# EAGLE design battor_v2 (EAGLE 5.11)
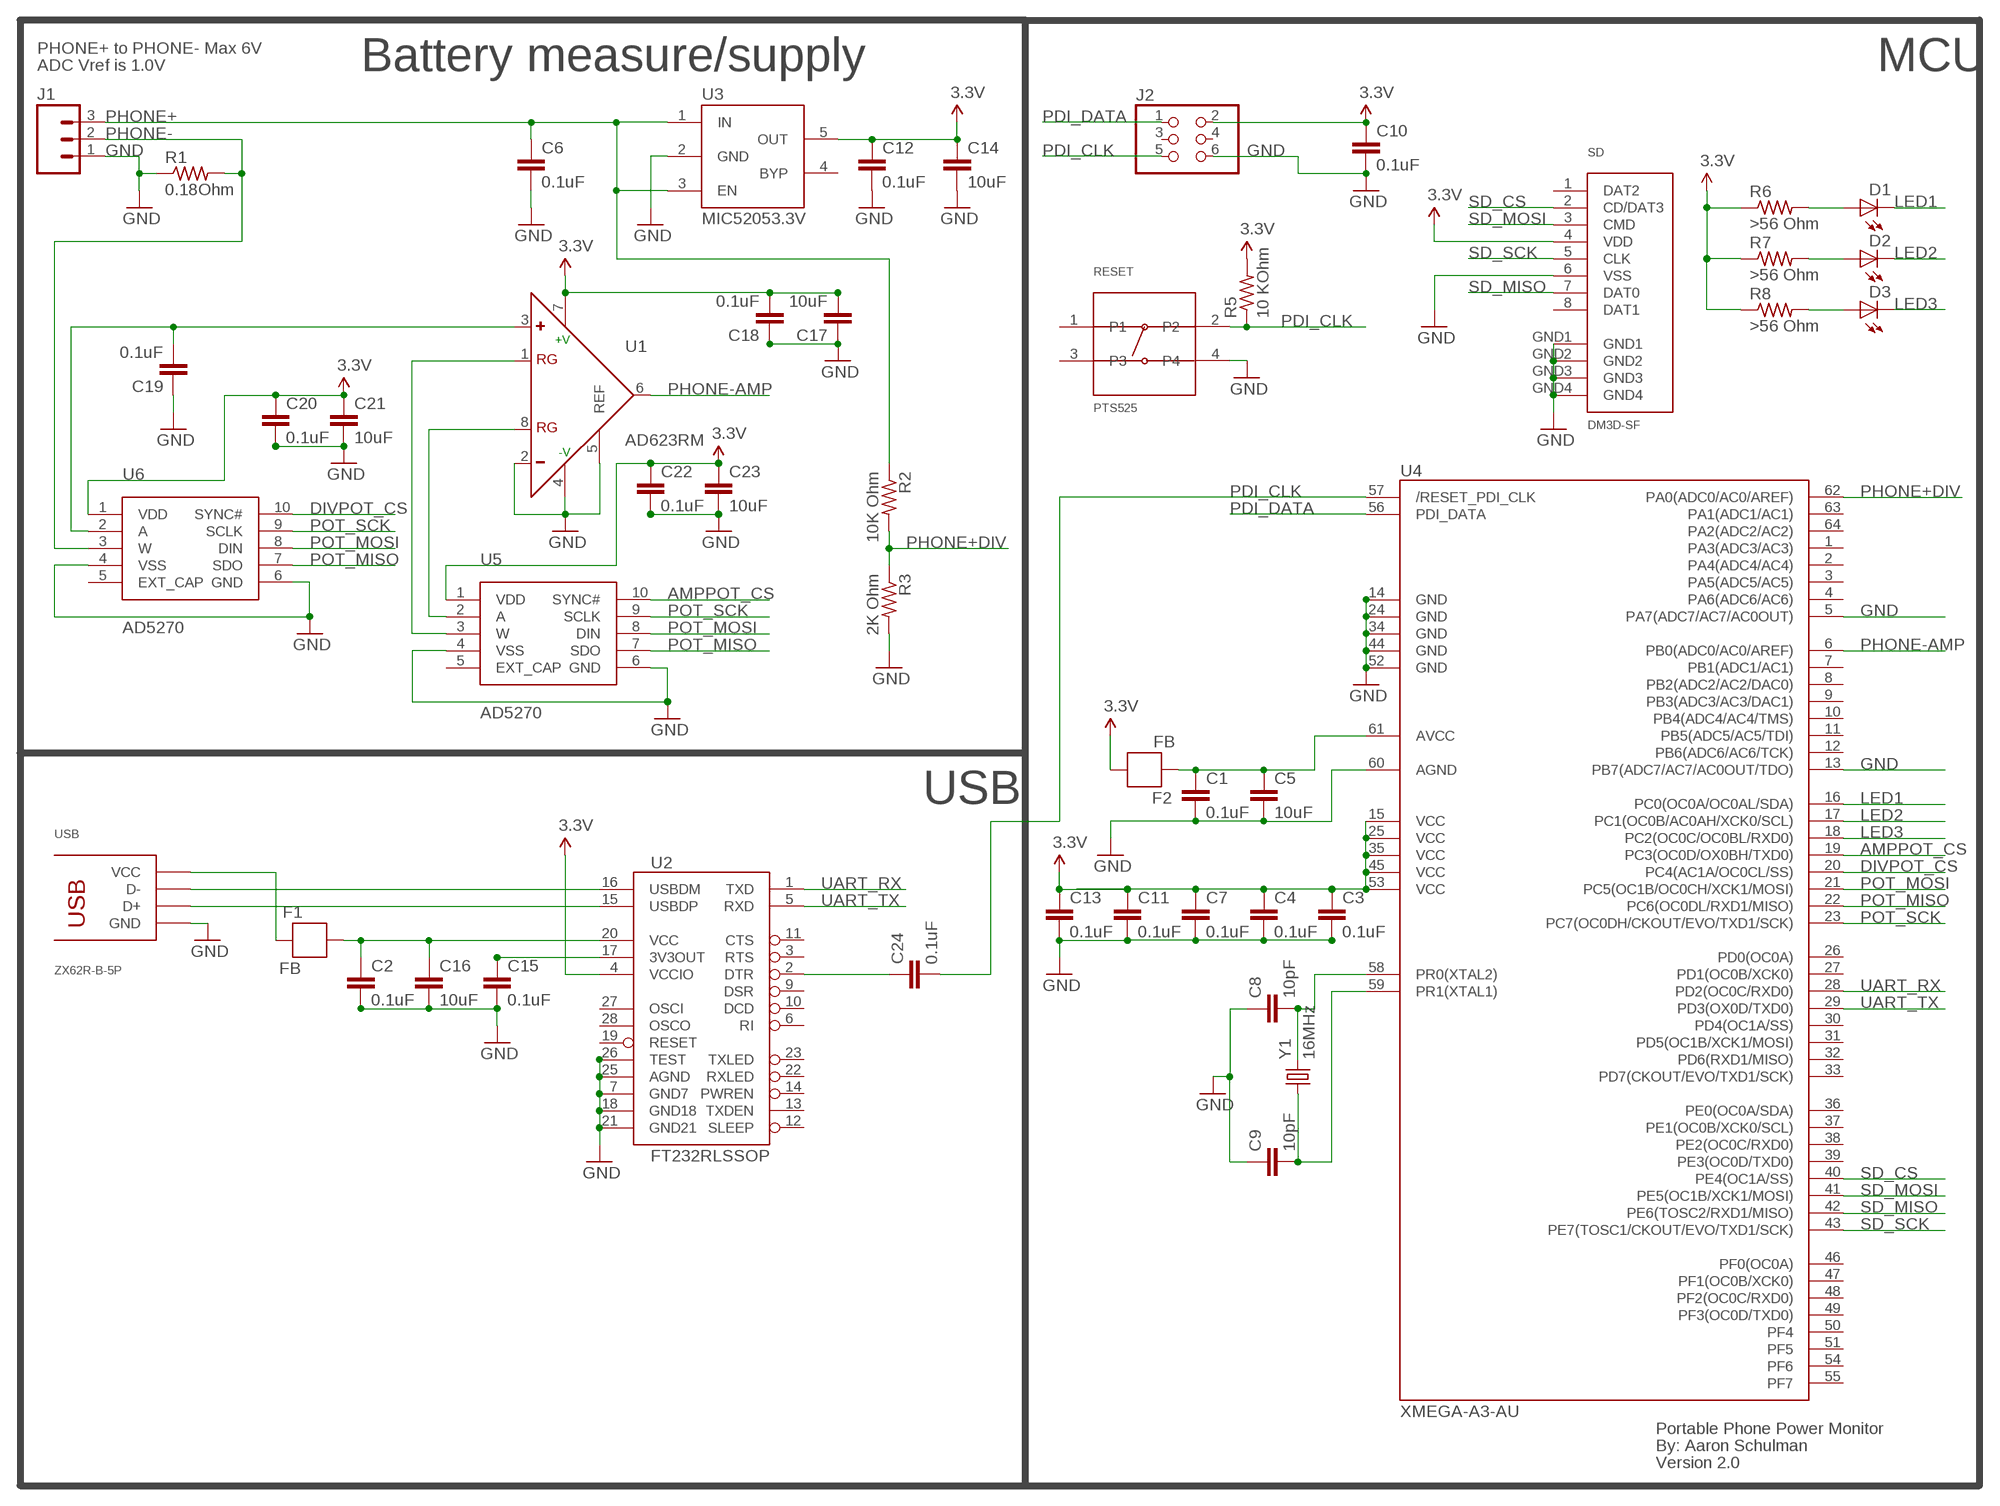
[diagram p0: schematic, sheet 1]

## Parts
C1  0.1uF  CAP0603-CAP  [0603-CAP]
C2  0.1uF  CAP0603-CAP  [0603-CAP]
C3  0.1uF  CAP0603-CAP  [0603-CAP]
C4  0.1uF  CAP0603-CAP  [0603-CAP]
C5  10uF  CAP0603-CAP  [0603-CAP]
C6  0.1uF  CAP0603-CAP  [0603-CAP]
C7  0.1uF  CAP0603-CAP  [0603-CAP]
C8  10pF  CAP0603-CAP  [0603-CAP]
C9  10pF  CAP0603-CAP  [0603-CAP]
C10  0.1uF  CAP0603-CAP  [0603-CAP]
C11  0.1uF  CAP0603-CAP  [0603-CAP]
C12  0.1uF  CAP0603-CAP  [0603-CAP]
C13  0.1uF  CAP0603-CAP  [0603-CAP]
C14  10uF  CAP0603-CAP  [0603-CAP]
C15  0.1uF  CAP0603-CAP  [0603-CAP]
C16  10uF  CAP0603-CAP  [0603-CAP]
C17  10uF  CAP0603-CAP  [0603-CAP]
C18  0.1uF  CAP0603-CAP  [0603-CAP]
C19  0.1uF  CAP0603-CAP  [0603-CAP]
C20  0.1uF  CAP0603-CAP  [0603-CAP]
C21  10uF  CAP0603-CAP  [0603-CAP]
C22  0.1uF  CAP0603-CAP  [0603-CAP]
C23  10uF  CAP0603-CAP  [0603-CAP]
C24  0.1uF  CAP0603-CAP  [0603-CAP]
D1  LED0603  [LED-0603]
D2  LED0603  [LED-0603]
D3  LED0603  [LED-0603]
F1  FB  [0603]
F2  FB  [0603]
J1  M03PTH  [1X03]
J2  PINHD-2X3  [2X03]
R1  0.18Ohm  R-US_R2512  [R2512]
R2  10K Ohm  R-US_R0603  [R0603]
R3  2K Ohm  R-US_R0603  [R0603]
R5  10 KOhm  R-US_R0603  [R0603]
R6  >56 Ohm  R-US_R0603  [R0603]
R7  >56 Ohm  R-US_R0603  [R0603]
R8  >56 Ohm  R-US_R0603  [R0603]
RESET  PTS525  [PT525]
SD  DM3D-SF  [DM3D-SF]
U1  AD623RM  [MSOP08]
U2  FT232RLSSOP  [SSOP28DB]
U3  MIC52053.3V  [SOT23-5]
U4  XMEGA-A3-AU  [TQFP64_14X14MM]
U5  AD5270  [MSOP10]
U6  AD5270  [MSOP10]
USB  ZX62R-B-5P  [ZX62R-B-5P]
Y1  16MHz  CRYSTAL5X3  [CRYSTAL-SMD-5X3]

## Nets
3.3V: C3.1 C4.1 C7.1 C10.1 C11.1 C12.1 C13.1 C14.1 C17.2 C18.2 C20.1 C21.1 C22.1 C23.1 F2.1 J2.2 R5.2 R6.1 R7.1 R8.1 SD.4(VDD) U1.7(+V) U2.4(VCCIO) U3.5(OUT) U4.15(VCC1) U4.25(VCC2) U4.35(VCC3) U4.45(VCC4) U4.53(VCC5) U5.1(VDD) U6.1(VDD)
AMPPOT_CS: U4.19(PC3(OC0D/OX0BH/TXD0)) U5.10(SYNC#)
DIVPOT_CS: U4.20(PC4(AC1A/OC0CL/SS)) U6.10(SYNC#)
GND: C1.2 C2.2 C3.2 C4.2 C5.2 C6.2 C7.2 C8.1 C9.1 C10.2 C11.2 C12.2 C13.2 C14.2 C15.2 C16.2 C17.1 C18.1 C19.1 C20.2 C21.2 C22.2 C23.2 J1.1 J2.6 R1.1 R3.2 RESET.4 SD.6(VSS) SD.GND1 SD.GND2 SD.GND3 SD.GND4 U1.2(-) U1.4(-V) U1.5(REF) U2.7(GND7) U2.18(GND18) U2.21(GND21) U2.25(AGND) U2.26(TEST) U3.2(GND) U4.5(PA7(ADC7/AC7/AC0OUT)) U4.13(PB7(ADC7/AC7/AC0OUT/TDO)) U4.14(GND1) U4.24(GND2) U4.34(GND3) U4.44(GND4) U4.52(GND5) U4.60(AGND) U5.4(VSS) U5.6(GND) U6.4(VSS) U6.6(GND) USB.P$5(GND)
LED1: D1.C U4.16(PC0(OC0A/OC0AL/SDA))
LED2: D2.C U4.17(PC1(OC0B/AC0AH/XCK0/SCL))
LED3: D3.C U4.18(PC2(OC0C/OC0BL/RXD0))
N$1: C8.2 U4.58(PR0(XTAL2)) Y1.3
N$2: C1.1 C5.1 F2.2 U4.61(AVCC)
N$3: C24.1 U2.2(DTR)
N$5: C19.2 U1.3(+) U6.2(A)
N$6: D1.A R6.2
N$7: U2.16(USBDM) USB.P$2(D-)
N$9: C9.2 U4.59(PR1(XTAL1)) Y1.1
N$11: U2.15(USBDP) USB.P$3(D+)
N$12: F1.2 USB.P$1(VCC)
N$13: C15.1 U2.17(3V3OUT)
N$14: C2.1 C16.1 F1.1 U2.20(VCC)
N$17: D3.A R8.2
N$18: D2.A R7.2
N$21: U1.8(RG) U5.2(A)
N$24: U1.1(RG) U5.3(W)
PDI_CLK: C24.2 J2.5 R5.1 RESET.2 U4.57(/RESET_PDI_CLK)
PDI_DATA: J2.1 U4.56(PDI_DATA)
PHONE+: C6.1 J1.3 R2.1 U3.1(IN) U3.3(EN)
PHONE+DIV: R2.2 R3.1 U4.62(PA0(ADC0/AC0/AREF))
PHONE-: J1.2 R1.2 U6.3(W)
PHONE-AMP: U1.6(OUT) U4.6(PB0(ADC0/AC0/AREF))
POT_MISO: U4.22(PC6(OC0DL/RXD1/MISO)) U5.7(SDO) U6.7(SDO)
POT_MOSI: U4.21(PC5(OC1B/OC0CH/XCK1/MOSI)) U5.8(DIN) U6.8(DIN)
POT_SCK: U4.23(PC7(OC0DH/CKOUT/EVO/TXD1/SCK)) U5.9(SCLK) U6.9(SCLK)
SD_CS: SD.2(CD/DAT3) U4.40(PE4(OC1A/SS))
SD_MISO: SD.7(DAT0) U4.42(PE6(TOSC2/RXD1/MISO))
SD_MOSI: SD.3(CMD) U4.41(PE5(OC1B/XCK1/MOSI))
SD_SCK: SD.5(CLK) U4.43(PE7(TOSC1/CKOUT/EVO/TXD1/SCK))
UART_RX: U2.1(TXD) U4.28(PD2(OC0C/RXD0))
UART_TX: U2.5(RXD) U4.29(PD3(OX0D/TXD0))
Unconnected: J2.3 J2.4 RESET.1 RESET.3 SD.1(DAT2) SD.8(DAT1) U2.3(RTS) U2.6(RI) U2.9(DSR) U2.10(DCD) U2.11(CTS) U2.12(SLEEP) U2.13(TXDEN) U2.14(PWREN) U2.19(RESET) U2.22(RXLED) U2.23(TXLED) U2.27(OSCI) U2.28(OSCO) U3.4(BYP) U4.1(PA3(ADC3/AC3)) U4.2(PA4(ADC4/AC4)) U4.3(PA5(ADC5/AC5)) U4.4(PA6(ADC6/AC6)) U4.7(PB1(ADC1/AC1)) U4.8(PB2(ADC2/AC2/DAC0)) U4.9(PB3(ADC3/AC3/DAC1)) U4.10(PB4(ADC4/AC4/TMS)) U4.11(PB5(ADC5/AC5/TDI)) U4.12(PB6(ADC6/AC6/TCK)) U4.26(PD0(OC0A)) U4.27(PD1(OC0B/XCK0)) U4.30(PD4(OC1A/SS)) U4.31(PD5(OC1B/XCK1/MOSI)) U4.32(PD6(RXD1/MISO)) U4.33(PD7(CKOUT/EVO/TXD1/SCK)) U4.36(PE0(OC0A/SDA)) U4.37(PE1(OC0B/XCK0/SCL)) U4.38(PE2(OC0C/RXD0)) U4.39(PE3(OC0D/TXD0)) U4.46(PF0(OC0A)) U4.47(PF1(OC0B/XCK0)) U4.48(PF2(OC0C/RXD0)) U4.49(PF3(OC0D/TXD0)) U4.50(PF4) U4.51(PF5) U4.54(PF6) U4.55(PF7) U4.63(PA1(ADC1/AC1)) U4.64(PA2(ADC2/AC2)) U5.5(EXT_CAP) U6.5(EXT_CAP)

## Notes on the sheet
- PHONE+ to PHONE- Max 6V
- ADC Vref is 1.0V | Battery measure/supply | MCU
- USB
- Portable Phone Power Monitor
- By: Aaron Schulman
- Version 2.0

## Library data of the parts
C1-C24 = SparkFun:CAP: Capacitor
D1-D3 = SparkFun:LED: LEDs
F1 F2 = SparkFun:FB
J1 = SparkFun:M03: Header 3 Standard 3-pin 0.1" header. Use with straight break away headers (SKU : PRT-00116), right angle break away headers (PRT-00553), swiss pins (PRT-00743), machine pins (PRT-00117), and female headers (PRT-00115). Molex polarized connector foot print use with SKU : PRT-08232 with associated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
J2 = SparkFun:PINHD-2X3: PIN HEADER
R1 = resistor:R-US_: RESISTOR, American symbol
R2 R3 R5-R8 = rcl:R-US_: RESISTOR, American symbol
RESET = phone_power_monitor:PTS525
SD = phone_power_monitor:DM3D-SF
U1 = analog-devices:AD623: Single-Supply, Rail-to-Rail, Low Cost Instrumentation Amplifier Source: http://www.analog.com/static/imported-files/data_sheets/AD623.pdf; MPN: AD623ARMZ; OC_FARNELL: 1660961; OC_NEWARK: 19M8824
U2 = SparkFun:FT232RL: USB UART FT232RL 4th Generation USB UART (USB <-> Serial) Controller. Spark Fun Electronics SKU : COM-00650
U3 = phone_power_monitor:MIC5205
U4 = SparkFun:XMEGA-A3: Atmel's 8/16-bit AVR XMEGA A3 Microcontroller - ATxmega256A3, etc.
U5 U6 = battor_v2:AD5270
USB = battor_v2:ZX62R-B-5P
Y1 = SparkFun:CRYSTAL: Crystals

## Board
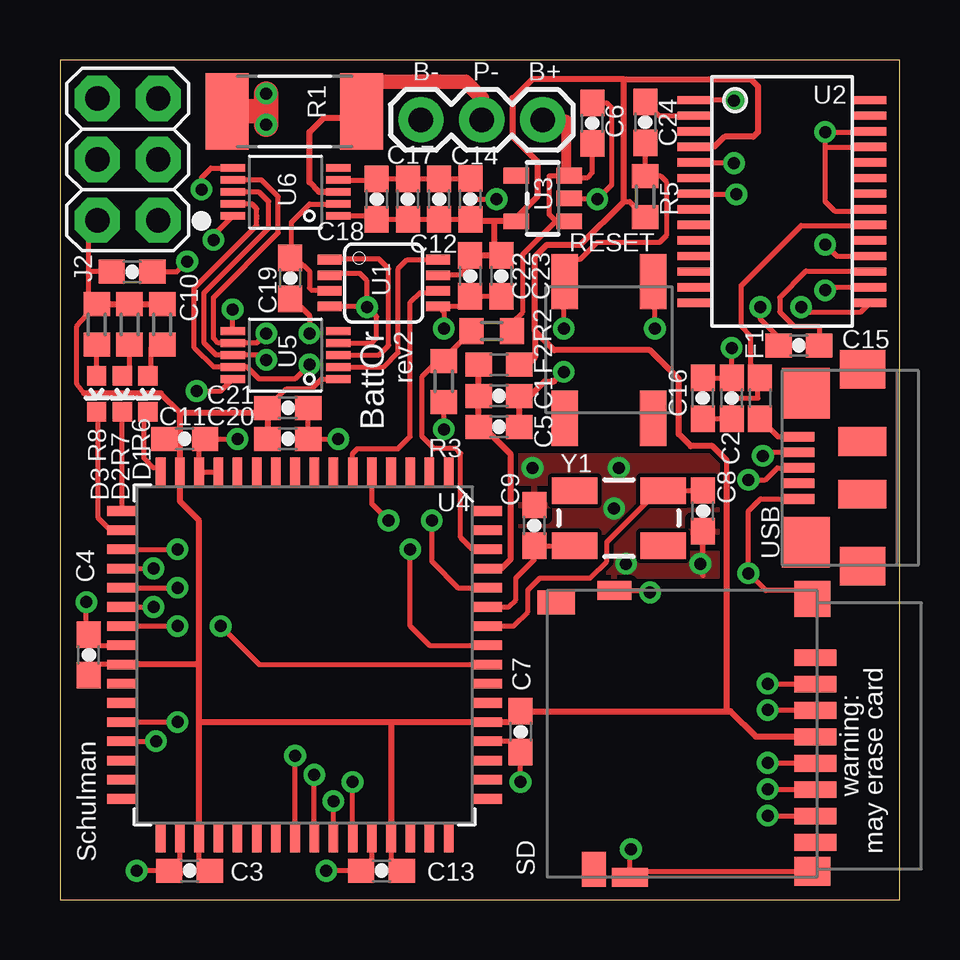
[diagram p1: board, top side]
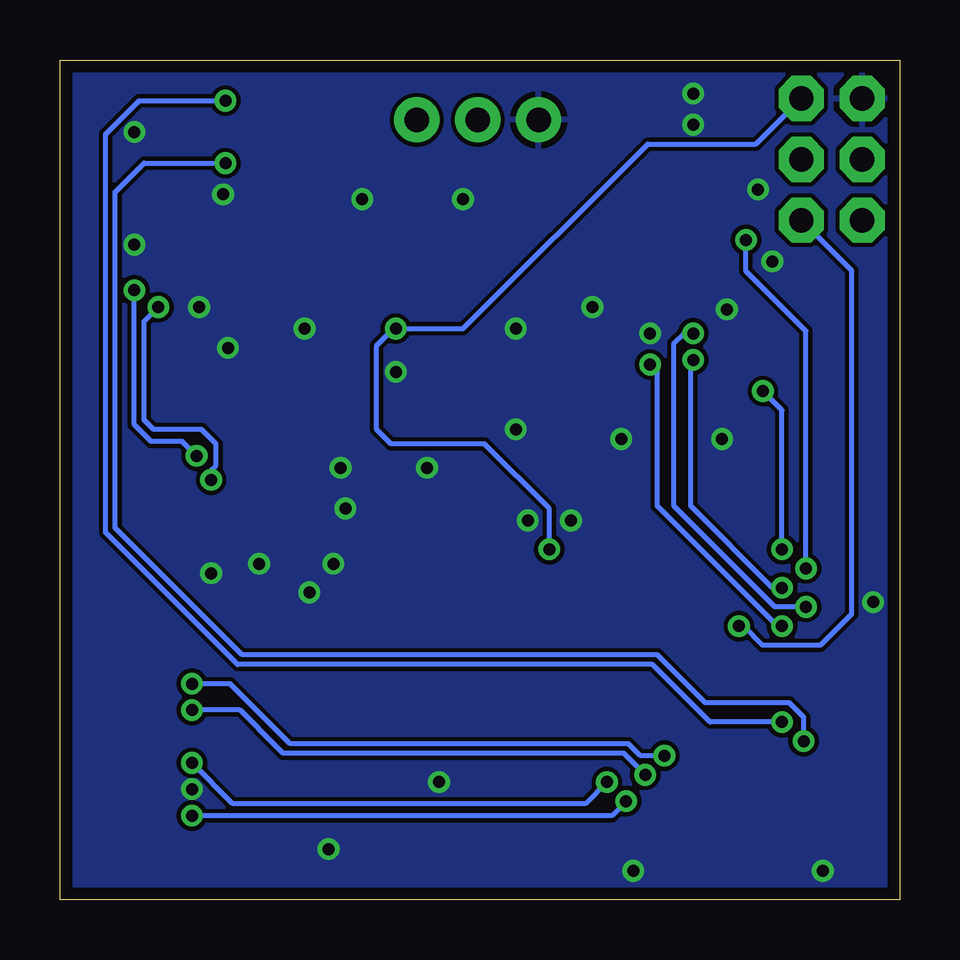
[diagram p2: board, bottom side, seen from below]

Size 35 x 35 mm. Coordinates in mm from the lower left corner, seen from the top.
Outline: 0,0 35,0 35,35 0,35 0,0
Copper layers (1*16): Top 0.0178mm / dielectric 1.4986mm / Bottom 0.0178mm
Design rules "SSC-EAGLE-2Lyr_v1.0.0.3 *": minimum track width 6mil, minimum drill 14mil, track to track 7mil, track to pad 7mil, pad to pad 7mil, via to via 7mil, smd to smd 7mil, copper to edge 20mil, drill to drill 16mil, minimum pad ring 8mil, minimum via ring 8mil, stop-mask expansion 3mil, vias tented up to drill 0mil, thermal gap 10mil

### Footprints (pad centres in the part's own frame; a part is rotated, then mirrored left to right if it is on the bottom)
0603-CAP = smd 1.1 x 1: 1 -0.85,0; 2 0.85,0
LED-0603 = smd 0.8 x 0.8: A 0,-0.75; C 0,0.75
0603 = smd 1.1 x 1: 1 -0.85,0; 2 0.85,0
1X03 = drill 1.016 pad 1.88 round: 1 0,0; 2 2.54,0; 3 5.08,0
2X03 = drill 1.016 pad 1.88 octagon: 1 -2.54,-1.27; 2 -2.54,1.27; 3 0,-1.27; 4 0,1.27; 5 2.54,-1.27; 6 2.54,1.27
R2512 = smd 1.8 x 3.2: 1 -2.8,0; 2 2.8,0
R0603 = smd 1 x 1.1: 1 -0.85,0; 2 0.85,0
PT525 = smd 2.3 x 1.1: 1 -2.85,1.85; 2 2.85,1.85; 3 -2.85,-1.85; 4 2.85,-1.85
DM3D-SF = smd 0.7 x 1.75: 1 7.7,-0.875; 2 6.6,-0.875; 3 5.5,-0.875; 4 4.4,-0.875; 5 3.3,-0.875; 6 2.2,-0.875; 7 1.1,-0.875; 8 0,-0.875 | smd 0.8 x 1.5: GND1 -1.45,6.85 | smd 0.8 x 1.4: GND2 10.5,7.5 | smd 1.5 x 1.5: GND3 10.15,-0.75 | smd 1.2 x 1.5: GND4 -1.2,-0.75 | smd 1 x 1.55: P$4 10,9.925 | smd 1.45 x 1: P$5 -1.125,8.35
MSOP08 = smd 0.4 x 1: 1 -0.976,-2.263; 2 -0.326,-2.263; 3 0.324,-2.263; 4 0.974,-2.263; 5 0.974,2.262; 6 0.324,2.262; 7 -0.326,2.262; 8 -0.976,2.262
SSOP28DB = smd 0.348 x 1.397: 1 -4.225,-3.656; 2 -3.575,-3.656; 3 -2.925,-3.656; 4 -2.275,-3.656; 5 -1.625,-3.656; 6 -0.975,-3.656; 7 -0.325,-3.656; 8 0.325,-3.656; 9 0.975,-3.656; 10 1.625,-3.656; 11 2.275,-3.656; 12 2.925,-3.656; 13 3.575,-3.656; 14 4.225,-3.656; 15 4.225,3.656; 16 3.575,3.656; 17 2.925,3.656; 18 2.275,3.656; 19 1.625,3.656; 20 0.975,3.656; 21 0.325,3.656; 22 -0.325,3.656; 23 -0.975,3.656; 24 -1.625,3.656; 25 -2.275,3.656; 26 -2.925,3.656; 27 -3.575,3.656; 28 -4.225,3.656
SOT23-5 = smd 0.65 x 1.06: 1 0.95,1.1; 2 0,1.1; 3 -0.95,1.1; 4 -0.95,-1.1; 5 0.95,-1.1
TQFP64_14X14MM = smd 0.4 x 1.27: 1 -6,-7.6; 2 -5.2,-7.6; 3 -4.4,-7.6; 4 -3.6,-7.6; 5 -2.8,-7.6; 6 -2,-7.6; 7 -1.2,-7.6; 8 -0.4,-7.6; 9 0.4,-7.6; 10 1.2,-7.6; 11 2,-7.6; 12 2.8,-7.6; 13 3.6,-7.6; 14 4.4,-7.6; 15 5.2,-7.6; 16 6,-7.6; 33 6,7.6; 34 5.2,7.6; 35 4.4,7.6; 36 3.6,7.6; 37 2.8,7.6; 38 2,7.6; 39 1.2,7.6; 40 0.4,7.6; 41 -0.4,7.6; 42 -1.2,7.6; 43 -2,7.6; 44 -2.8,7.6; 45 -3.6,7.6; 46 -4.4,7.6; 47 -5.2,7.6; 48 -6,7.6 | smd 1.27 x 0.4: 17 7.6,-6; 18 7.6,-5.2; 19 7.6,-4.4; 20 7.6,-3.6; 21 7.6,-2.8; 22 7.6,-2; 23 7.6,-1.2; 24 7.6,-0.4; 25 7.6,0.4; 26 7.6,1.2; 27 7.6,2; 28 7.6,2.8; 29 7.6,3.6; 30 7.6,4.4; 31 7.6,5.2; 32 7.6,6; 49 -7.6,6; 50 -7.6,5.2; 51 -7.6,4.4; 52 -7.6,3.6; 53 -7.6,2.8; 54 -7.6,2; 55 -7.6,1.2; 56 -7.6,0.4; 57 -7.6,-0.4; 58 -7.6,-1.2; 59 -7.6,-2; 60 -7.6,-2.8; 61 -7.6,-3.6; 62 -7.6,-4.4; 63 -7.6,-5.2; 64 -7.6,-6
MSOP10 = smd 0.32 x 1.02: 1 -1,-2.2; 2 -0.5,-2.2; 3 0,-2.2; 4 0.5,-2.2; 5 1,-2.2; 6 1,2.2; 7 0.5,2.2; 8 0,2.2; 9 -0.5,2.2; 10 -1,2.2
ZX62R-B-5P = smd 0.4 x 1.35: P$1 1.3,-0.675; P$2 0.65,-0.675; P$3 0,-0.675; P$4 -0.65,-0.675; P$5 -1.3,-0.675 | smd 2.1 x 2: P$6 -3.1,-1; P$7 3.1,-1 | smd 1.6 x 1.9: P$8 -4.1,-3.35; P$9 4.1,-3.35 | smd 1.2 x 2: P$10 -1.1,-3.35; P$11 1.1,-3.35
CRYSTAL-SMD-5X3 = smd 1.9 x 1.1: 1 -1.85,-1.15; 2 1.85,-1.15; 3 1.85,1.15; 4 -1.85,1.15

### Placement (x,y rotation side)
C1  18.3,21 0 top
C2  28,20.9 90 top
C3  5.4,1.2 180 top
C4  1.2,10.2 90 top
C5  18.3,19.7 0 top
C6  22.2,32.37 90 top
C7  19.2,7 270 top
C8  26.8,16.2 90 top
C9  19.77,15.6 270 top
C10  3.01,26.17 0 top
C11  5.2,19.2 0 top
C12  15.81,29.2 90 top
C13  13.4,1.2 180 top
C14  17.11,29.21 90 top
C15  30.8,23.1 180 top
C16  26.8,20.9 90 top
C17  14.5,29.2 270 top
C18  13.2,29.2 270 top
C19  9.6,25.9 90 top
C20  9.5,19.2 0 top
C21  9.5,20.5 0 top
C22  17.1,26 270 top
C23  18.4,26 270 top
C24  24.4,32.4 270 top
D1  3.67,21.09 180 top
D2  2.6,21.09 180 top
D3  1.53,21.09 180 top
F1  29.18,20.9 270 top
F2  18.3,22.3 180 top
J1  15.04,32.5 0 top
J2  2.83,30.86 90 top
R1  9.77,32.86 0 top
R2  18,23.7 180 top
R3  16,21.6 270 top
R5  24.4,29.3 270 top
R6  4.27,23.98 270 top
R7  2.9,23.98 270 top
R8  1.53,23.98 270 top
RESET  22.89,22.91 90 top
SD  30.61,2.38 90 top
U1  13.5,25.7 270 top
U2  30.1,29.1 270 top
U3  20.12,29.23 270 top
U4  10.2,10.2 180 top
U5  9.4,22.7 90 top
U6  9.4,29.5 90 top
USB  30.1,18 90 top
Y1  23.3,15.9 0 top

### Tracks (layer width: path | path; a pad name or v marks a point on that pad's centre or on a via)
3.3V
  Top 0.2: 6.25,1 5.8,1 U4.35 | 1,9.8 1.2,9.8 U4.25 | 14.25,1 13.8,1 U4.45 | 1.2,26.2 1.2,24.73 R8.1 | 31.09,6.8 SD.4 31.47,6.8 | 18.75,7.4 C7.1 | U2.4 26.44,31.4 | 16.97,28.28 C14.1 | C12.1 15.7,28.32 | 17.33,28.28 16.97,28.28 | C10.1 2.06,26.2 1.2,26.2 | 5,19.2 C11.1 | R8.1 1.53,24.7 | U2.4 26.42,31.4 | 26.47,31.4 U2.4 | 27.7,7.85 27.8,7.95 | C12.1 15.61,28.29 15.57,28.25 15.47,28.35 C17.2 C18.2 | 1,21.1 0.7,21.5 0.7,23.9 R8.1 | 1.2,26.2 1.2,27.96 J2.2 | C22.1 17.05,26.4 16.68,26.03 U1.7 | R5.2 23.75,29.1 23.5,29.1 | C18.2 13.2,28.2 | C18.2 12.95,28.5 U6.1 | 18.1,27.15 C23.1 | 16.97,28.28 16.89,28.35 C12.1 | U5.1 10.9,21.7 10.5,21.3 9.45,21.3 C21.1 | 27.8,17.8 27.8,18.3
  Top 0.25: 13.8,7.4 U4.45 | 13.8,7.4 U4.53 18.75,7.4 | U4.35 5.8,7.4 | 5.8,7.4 13.8,7.4 | R8.1 R7.1 R6.1 | 5.8,9.8 U4.25 | 5.8,7.4 5.8,9.8 | 18.1,28.28 U3.5 19.02,28.42 19.9,29.3 19.9,30.77 19.87,30.8 | 18.1,28.28 17.33,28.28 | C7.1 27.7,7.85 27.95,7.85 29,6.8 31.47,6.8 | 23.5,34.2 19.7,34.2 18.91,33.41 18.86,33.41 18.86,31.81 19.87,30.8 | 23.5,34.2 28.8,34.2 29.1,33.9 29.1,32 28.9,31.8 27.7,31.8 27.3,31.4 26.47,31.4 | 23.5,34.2 23.5,29.1 21.7,27.3 20.3,27.3 19.8,26.8 19.8,23.7 | 5.8,9.8 5.8,15.8 5,16.6 U4.15 5,19.2 5,20.3 | 5,20.3 4.2,21.1 1,21.1 | 19.87,30.8 19.9,30.8 | 27.8,7.95 27.8,17.8 | 19.8,23.7 20.6,22.9 24.6,22.9 25.8,21.7 25.8,19.4 26.3,18.9 27.2,18.9 27.8,18.3 | 15.61,28.29 15.8,28.1 | C14.1 17.04,28.29 | C23.1 C22.1 | 18.1,28.28 18.1,27.15 | 19.8,23.7 19.8,22.6 19.4,22.2 F2.1 | 5,20.3 8.45,20.3 C21.1 C20.1
  Top 0.305: R8.1 1.13,24.7
  Top 0.406: C3.1 6.25,1 | 14.25,1 C13.1 | 1.2,9.8 C4.1
AMPPOT_CS  (via drill 0.5)
  Top 0.2: U4.19 v4.9,14.6 | v5.7,21.2 6.7,21.2 U5.10
  Bottom 0.2: v4.9,14.6 4.9,20.4 v5.7,21.2
DIVPOT_CS  (via drill 0.5)
  Top 0.2: U4.20 v3.9,13.8 | v6.4,27.5 6.4,27.7 U6.10
  Bottom 0.2: v3.9,13.8 3.9,23.7 6.4,26.2 v6.4,27.5
GND  (via drill 0.5, 0.5 pad 0.25)
  Top 0.2: 5,1.2 5,1 | 5,1.2 U4.34 | U4.24 1.2,10.6 1,10.6 | 5.8,19.4 U4.14 U4.13 | 19.2,6.6 19.4,6.6 | 5,1.2 C3.2 v3.2,1.2 | v19.2,4.9 C7.2 19.2,6.6 | C11.2 v7.4,19.2 | 1.1,11.1 v1.1,12.4 | U4.44 13,1 12.55,1 | C13.2 v11.1,1.2 | SD.6 31.09,4.6 v29.5,4.6 | SD.GND3 30.96,12.88 | 22.7,12.88 SD.GND2 24.6,12.88 v24.6,12.8 | C17.1 14.4,29.97 14.7,29.97 14.72,29.99 | v23.8,2.1 23.76,2.1 SD.GND1 23.76,1.18 SD.GND4 | 19.2,6.6 U4.52 | U3.2 22.4,29.23 | U2.21 33.76,28.8 | 33.76,31.4 U2.25 31.9,31.38 | U2.26 33.76,32 v31.9,32 31.9,31.38 | v28.2,29.4 26.44,29.4 U2.7 | U2.21 33.76,28.7 | C16.2 C2.2 v28,23 | 29.7,23.1 C15.2 29.95,23.45 29.2,24.2 v29.2,24.7 | v18.2,29.2 17.07,29.2 C14.2 17.04,29.99 16.98,30.05 C12.2 C17.1 | v24.8,23.8 24.8,25.76 RESET.4 | 30.96,12.88 30.96,12.9 | 3.76,26.1 C10.2 4.87,26.17 v5.3,26.6 | 31.9,31.38 31.9,29.1 32.3,28.7 33.68,28.7 U2.21 | 26.8,13.5 C8.1 | U2.18 32.38,26.82 v31.9,27.3 | v22.4,29.2 23,29.8 23,33 22.8,33.2 22.21,33.2 C6.2 | U4.5 13,16.5 v13.7,15.8 | C17.1 14.35,29.95 14.25,30.05 C18.1 | C18.1 13.25,30 | C17.1 14.47,30.02 | C18.1 13.15,30 U6.4 | C23.2 C22.2 16.68,24.73 U1.5 16,24.49 v16,23.8 | U4.60 16.6,13 15.5,14.1 v15.5,15.8 | U1.2 11.16,26.1 12.5,26.1 12.8,25.8 v12.8,24.7 | v16,19.6 R3.2 | v11.6,19.2 C20.2 C21.2 | U1.4 12.77,24.73 v12.8,24.7 | U5.4 13,23.2 13.2,23.4 13.2,24.3 v12.8,24.7 | v10.4,23.6 10.4,24.35 9.7,25.05 C19.1 | v5.9,29.6 5.9,30.1 6.3,30.5 U6.6 | U5.6 v7.2,24.6 | USB.P$5 29.2,16.7 28.7,16.2 v28.7,13.6 29.42,12.88 30.96,12.88
  Top 0.25: C1.2 C5.2 19.15,20.55 20.2,21.6 20.6,21.6 v21,22 | 22.4,29.23 v22.4,29.2
  Top 0.406: 5.8,19.4 6.25,19.4 C11.2 | 1.2,10.6 C4.2 1.1,11.1 | C13.2 12.55,1
  Top 1.016: R1.1 8.6,32.85 v8.6,32.3 v8.6,33.6
  other vias: 19.7,18 23.3,18 23.1,16.3 23.6,14 26.7,14
  pour Bottom: 0.5,0.5 34.5,0.5 34.5,34.5 0.5,34.5
  pour Top: 27.8,18.5 18.8,18.5 18.8,13.5 27.8,13.5
LED1
  Top 0.2: 3.5,20.4 3.87,20.4 D1.C 3.5,20.17 3.5,18.4 3.9,18 4.2,18 U4.16
LED2
  Top 0.2: U4.17 D2.C
LED3
  Top 0.2: D3.C 1.6,20.27 1.6,15.9 2.1,15.4 U4.18
N$1
  Top 0.2: C8.2 26.85,17.05 Y1.3 24.95,17.05 22.8,14.9 22.8,14.1 22.1,13.4 20,13.4 19.5,12.9 19.5,12 18.9,11.4 U4.58
N$2
  Top 0.25: F2.2 C1.1 C5.1 17.65,19.7 18.8,18.55 18.8,14.2 18.4,13.8 U4.61
N$3
  Top 0.2: C24.1 24.98,32.67 U2.2
N$5
  Top 0.2: 11.21,25.4 10.5,25.4 10.4,25.5 10.4,26.2 9.85,26.75 C19.2 | 9.65,26.95 9.65,28.25 10.4,29 U6.2
  Top 0.25: C19.2 9.65,26.95 | 11.21,25.4 U1.3
N$6
  Top 0.2: D1.A 3.8,21.84 3.8,23 R6.2
N$7  (via drill 0.5)
  Top 0.2: U2.16 32.02,25.52 v31.9,25.4 | USB.P$2 29.45,18.65 v29.3,18.5
  Bottom 0.2: v29.3,18.5 29.9,19.1 31.2,19.1 31.9,19.8 v31.9,25.4
N$9
  Top 0.2: Y1.1 C9.2 19.77,14.17 19,13.4 19,12.5 18.7,12.2 U4.59
N$11  (via drill 0.5)
  Top 0.2: 33.68,24.8 U2.15 33.38,24.5 31.1,24.5 v30.9,24.7 | USB.P$3 29.9,18 29.4,17.5 v28.7,17.5
  Bottom 0.2: v30.9,24.7 31.5,24.1 31.5,20 31.1,19.6 29.1,19.6 28.5,19 28.5,18.1 28.7,17.9 v28.7,17.5
N$12
  Top 0.2: F1.2 28.8,19.77 | F1.2 29.1,20.03 | USB.P$1 29.93,19.3 F1.2
N$13
  Top 0.2: C15.1 31.65,23.9 30.6,23.9 30,24.5 30,25.1 31.1,26.2 33.73,26.2 U2.17
N$14
  Top 0.2: C2.1 28.2,20.1 | C16.1 C2.1 | C2.1 28,20.9 29.1,20.9 29.1,21.75 F1.1 29.08,22.02 28.8,22.3 28.8,23.5 28.4,23.9 28.4,25.6 30.9,28.1 33.73,28.1 U2.20 33.76,28.1
N$17
  Top 0.2: D3.A R8.2
N$18
  Top 0.2: D2.A 2.9,21.84 2.9,23.1 R7.2
N$21
  Top 0.2: U1.8 14.48,26.68 14.1,26.3 14.1,22.8 13.5,22.2 U5.2
N$24
  Top 0.2: U5.3 13.3,22.7 13.7,23.1 13.7,26.3 13.3,26.7 11.26,26.7 U1.1
PDI_CLK  (via drill 0.5)
  Top 0.2: v21,23.8 21,26.16 RESET.2 21.04,26.2 21.54,26.7 21.7,26.7 22.4,27.4 25,27.4 25.3,27.7 25.3,29.9 25.05,30.15 R5.1 C24.2 | U4.57 15.4,10.6 14.6,11.4 v14.6,14.6
  Bottom 0.2: J2.5 5.99,31.5 10.5,31.5 18.2,23.8 v21,23.8 21.1,23.8 21.8,23.1 21.8,19.6 21.2,19 19.8,19 19.3,19 17.3,19 14.6,16.3 v14.6,14.6
PDI_DATA  (via drill 0.5)
  Top 0.2: U4.56 8.3,9.8 v6.7,11.4
  Bottom 0.2: J2.1 2,26.22 2,11.9 3.3,10.6 5.7,10.6 6.5,11.4 v6.7,11.4
PHONE+
  Top 0.2: C6.1 22.2,30.3 22,30.1 21.2,30.1 21.2,30.15 U3.3 | 20.68,28.28 U3.1 | U3.3 20.4,30.18 20.4,28.55 20.68,28.28 | U3.3 21.12,30.28 | 20.68,28.28 19.3,26.9 19.3,24.5 18.85,24.05 R2.1
  Top 0.254: J1.3 20.17,32.5
  Top 0.406: J1.3 21.12,32.5 21.12,30.28
PHONE+DIV
  Top 0.2: U4.62 17.2,14.6 16.7,15.1 16.7,18.6 16.5,18.8 15.6,18.8 15.1,19.3 15.1,21.8 15.7,22.4 15.95,22.4 R3.1 | R3.1 16.05,22.6 | R3.1 16,22.8 | R2.2 16,22.55 R3.1
PHONE-
  Top 0.2: 12.5,32.6 12.5,32.78 R1.2 | 17.6,32.6 17.6,32.52 J1.2
  Top 0.25: 12.5,32.6 11,32.6 10.4,32 10.4,29.9 10.8,29.5 U6.3
  Top 0.406: 12.5,32.6 12.5,34.1
  Top 0.6: 16.9,34.1 17.6,33.4 17.6,32.6
  Top 0.61: 12.5,34.1 16.9,34.1
PHONE-AMP
  Top 0.2: U1.6 15.69,25.3 15,25.3 14.6,24.9 14.6,19.3 14.1,18.8 12.4,18.8 12.2,18.6 U4.6
POT_MISO  (via drill 0.5)
  Top 0.2: U4.22 v3.9,12.2 | U6.7 8.4,30 9.1,29.3 9.1,27.8 6.4,25.1 6.4,23.4 6.6,23.2 U5.7 8.2,23.2 v8.6,23.6
  Bottom 0.2: v3.9,12.2 5.2,12.2 9.4,16.4 9.4,23.2 9,23.6 v8.6,23.6
POT_MOSI  (via drill 0.5)
  Top 0.2: U4.21 v4.9,13 | U6.8 8.3,29.5 8.7,29.1 8.7,28 6,25.3 6,23.2 6.5,22.7 U5.8 8.4,22.7 v8.6,22.5
  Bottom 0.2: v4.9,13 5.3,13 8.7,16.4 8.7,22.4 v8.6,22.5
POT_SCK  (via drill 0.5)
  Top 0.2: U4.23 v4.9,11.4 | U6.9 8,29 8.2,28.8 8.2,28.5 8.2,28.4 8.2,28.1 5.6,25.5 5.6,23 6.4,22.2 U5.9 7.8,22.2 8.3,21.7 9.8,21.7 v10.4,22.3
  Bottom 0.2: v4.9,11.4 5.1,11.4 10.1,16.4 10.1,22 v10.4,22.3
SD_CS  (via drill 0.5 pad 0.25)
  Top 0.2: U4.40 v9.8,6 | SD.2 31.09,9 v29.5,9
  Bottom 0.2: v29.5,9 27.9,9 25.4,6.5 11.3,6.5 10.8,6 v9.8,6
SD_MISO  (via drill 0.5 pad 0.25)
  Top 0.2: U4.42 v11.4,4.1 | SD.7 31.09,3.5 v29.5,3.5
  Bottom 0.2: v11.4,4.1 12,3.5 v29.5,3.5
SD_MOSI  (via drill 0.5 pad 0.25)
  Top 0.2: U4.41 v10.6,5.2 | SD.3 31.09,7.9 v29.5,7.9
  Bottom 0.2: v29.5,7.9 27.5,7.9 25.95,6.35 25.7,6.1 11.5,6.1 v10.6,5.2
SD_SCK  (via drill 0.5 pad 0.25)
  Top 0.2: U4.43 v12.2,4.9 | SD.5 31.09,5.7 v29.5,5.7
  Bottom 0.2: v12.2,4.9 13.1,4 27.8,4 v29.5,5.7
UART_RX  (via drill 0.5)
  Top 0.2: U4.28 v4.9,7.4 | U2.1 28.1,33.33 v28.1,33.3
  Bottom 0.2: v28.1,33.3 31.7,33.3 33.1,31.9 33.1,15.3 27.6,9.8 10.3,9.8 7.9,7.4 v4.9,7.4
UART_TX  (via drill 0.5)
  Top 0.2: U4.29 v4,6.6 | v28.1,30.7 26.44,30.7 U2.5
  Bottom 0.2: v28.1,30.7 31.5,30.7 32.7,29.5 32.7,15.5 27.4,10.2 10.1,10.2 8.1,8.2 4.6,8.2 4,7.6 v4,6.6

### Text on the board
tPlace: B- | P- | B+ | BattOr | rev2 | Schulman | warning: | may erase card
